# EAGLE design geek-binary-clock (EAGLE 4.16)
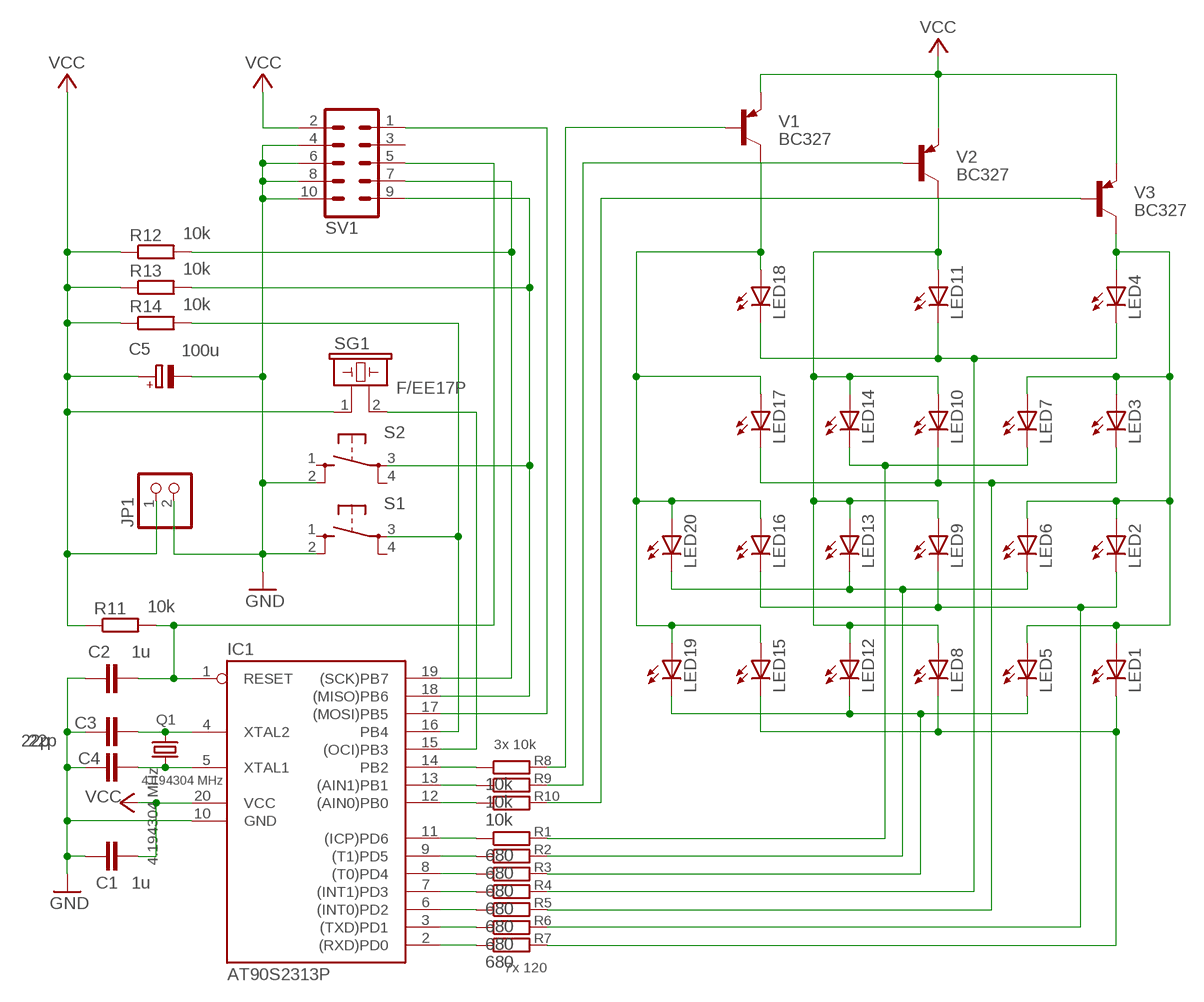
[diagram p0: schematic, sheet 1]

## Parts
C1  1u  C-EU050-025X075  [C050-025X075]
C2  1u  C-EU050-025X075  [C050-025X075]
C3  22p  C-EU025-024X044  [C025-024X044]
C4  22p  C-EU025-024X044  [C025-024X044]
C5  100u  CPOL-EUE15-6AXIAL  [E15-6]
IC1  AT90S2313P  [DIL20]
JP1  PINHD-1X2  [1X02]
LED1  LED5MM  [LED5MM]
LED2  LED5MM  [LED5MM]
LED3  LED5MM  [LED5MM]
LED4  LED5MM  [LED5MM]
LED5  LED5MM  [LED5MM]
LED6  LED5MM  [LED5MM]
LED7  LED5MM  [LED5MM]
LED8  LED5MM  [LED5MM]
LED9  LED5MM  [LED5MM]
LED10  LED5MM  [LED5MM]
LED11  LED5MM  [LED5MM]
LED12  LED5MM  [LED5MM]
LED13  LED5MM  [LED5MM]
LED14  LED5MM  [LED5MM]
LED15  LED5MM  [LED5MM]
LED16  LED5MM  [LED5MM]
LED17  LED5MM  [LED5MM]
LED18  LED5MM  [LED5MM]
LED19  LED5MM  [LED5MM]
LED20  LED5MM  [LED5MM]
Q1  4.194304 MHz  HC49U-V  [HC49U-V]
R1  680  R-EU_0207/10  [0207/10]
R2  680  R-EU_0207/10  [0207/10]
R3  680  R-EU_0207/10  [0207/10]
R4  680  R-EU_0207/10  [0207/10]
R5  680  R-EU_0207/10  [0207/10]
R6  680  R-EU_0207/10  [0207/10]
R7  680  R-EU_0207/10  [0207/10]
R8  10k  R-EU_0207/10  [0207/10]
R9  10k  R-EU_0207/10  [0207/10]
R10  10k  R-EU_0207/10  [0207/10]
R11  10k  R-EU_0207/10  [0207/10]
R12  10k  R-EU_0207/10  [0207/10]
R13  10k  R-EU_0207/10  [0207/10]
R14  10k  R-EU_0207/10  [0207/10]
S1  10-XX  [B3F-10XX]
S2  10-XX  [B3F-10XX]
SG1  F/EE17P  [F/EE17P]
SV1  ML10L  [ML10L]
V1  BC327  [TO92]
V2  BC327  [TO92]
V3  BC327  [TO92]

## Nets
/RESET: C2.2 IC1.1(RESET) R11.2 SV1.5
A0: LED1.A LED2.A LED3.A LED4.A LED5.A LED6.A LED7.A V3.3(C)
A1: LED8.A LED9.A LED10.A LED11.A LED12.A LED13.A LED14.A V2.3(C)
A2: LED15.A LED16.A LED17.A LED18.A LED19.A LED20.A V1.3(C)
D0: LED1.K(C) LED8.K(C) LED15.K(C) R7.2
D1: LED2.K(C) LED9.K(C) LED16.K(C) R6.2
D2: LED3.K(C) LED10.K(C) LED17.K(C) R5.2
D3: LED4.K(C) LED11.K(C) LED18.K(C) R4.2
D4: LED5.K(C) LED12.K(C) LED19.K(C) R3.2
D5: LED6.K(C) LED13.K(C) LED20.K(C) R2.2
D6: LED7.K(C) LED14.K(C) R1.2
GND: C1.1 C2.1 C3.1 C4.1 C5.- IC1.10(GND) JP1.2 S1.2 S2.2 SV1.4 SV1.6 SV1.8 SV1.10
N$1: IC1.11((ICP)PD6) R1.1
N$2: IC1.9((T1)PD5) R2.1
N$3: IC1.8((T0)PD4) R3.1
N$4: IC1.7((INT1)PD3) R4.1
N$5: IC1.6((INT0)PD2) R5.1
N$6: IC1.3((TXD)PD1) R6.1
N$7: IC1.2((RXD)PD0) R7.1
N$8: C3.2 IC1.4(XTAL2) Q1.1
N$9: IC1.16(PB4) R14.2 S1.3
N$10: R9.2 V2.2(B)
N$11: R10.2 V3.2(B)
N$12: R8.2 V1.2(B)
N$13: IC1.12((AIN0)PB0) R10.1
N$14: IC1.13((AIN1)PB1) R9.1
N$15: IC1.14(PB2) R8.1
N$16: C4.2 IC1.5(XTAL1) Q1.2
N$17: IC1.15((OCI)PB3) SG1.2
PB5: IC1.17((MOSI)PB5) SV1.1
PB6: IC1.18((MISO)PB6) R13.2 S2.3 SV1.9
PB7: IC1.19((SCK)PB7) R12.2 SV1.7
VCC: C1.2 C5.+ IC1.20(VCC) JP1.1 R11.1 R12.1 R13.1 R14.1 SG1.1 SV1.2 V1.1(E) V2.1(E) V3.1(E)
Unconnected: S1.1 S1.4 S2.1 S2.4 SV1.3

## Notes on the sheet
- 3x 10k
- 4.194304 MHz
- 7x 120

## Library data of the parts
C1-C4 = rcl:C-EU: CAPACITOR, European symbol
C5 = rcl:CPOL-EU: POLARIZED CAPACITOR, European symbol
IC1 = avr:AT90S2313: MICROCONTROLLER 2 Kbytes FLASH 128 bytes SRAM 128 bytes EEPROM UART
JP1 = pinhead:PINHD-1X2: PIN HEADER
LED1-LED20 = led:LED: LED
Q1 = QUARTZ:HC49U-V
R1-R14 = rcl:R-EU_: RESISTOR, European symbol
S1 S2 = KEYOMRON:10-XX
SG1 = buzzer:F/EE17P: BUZZER
SV1 = con-harting-ml:ML10: HARTING
V1-V3 = transistor-pnp:BC327: PNP Transistor

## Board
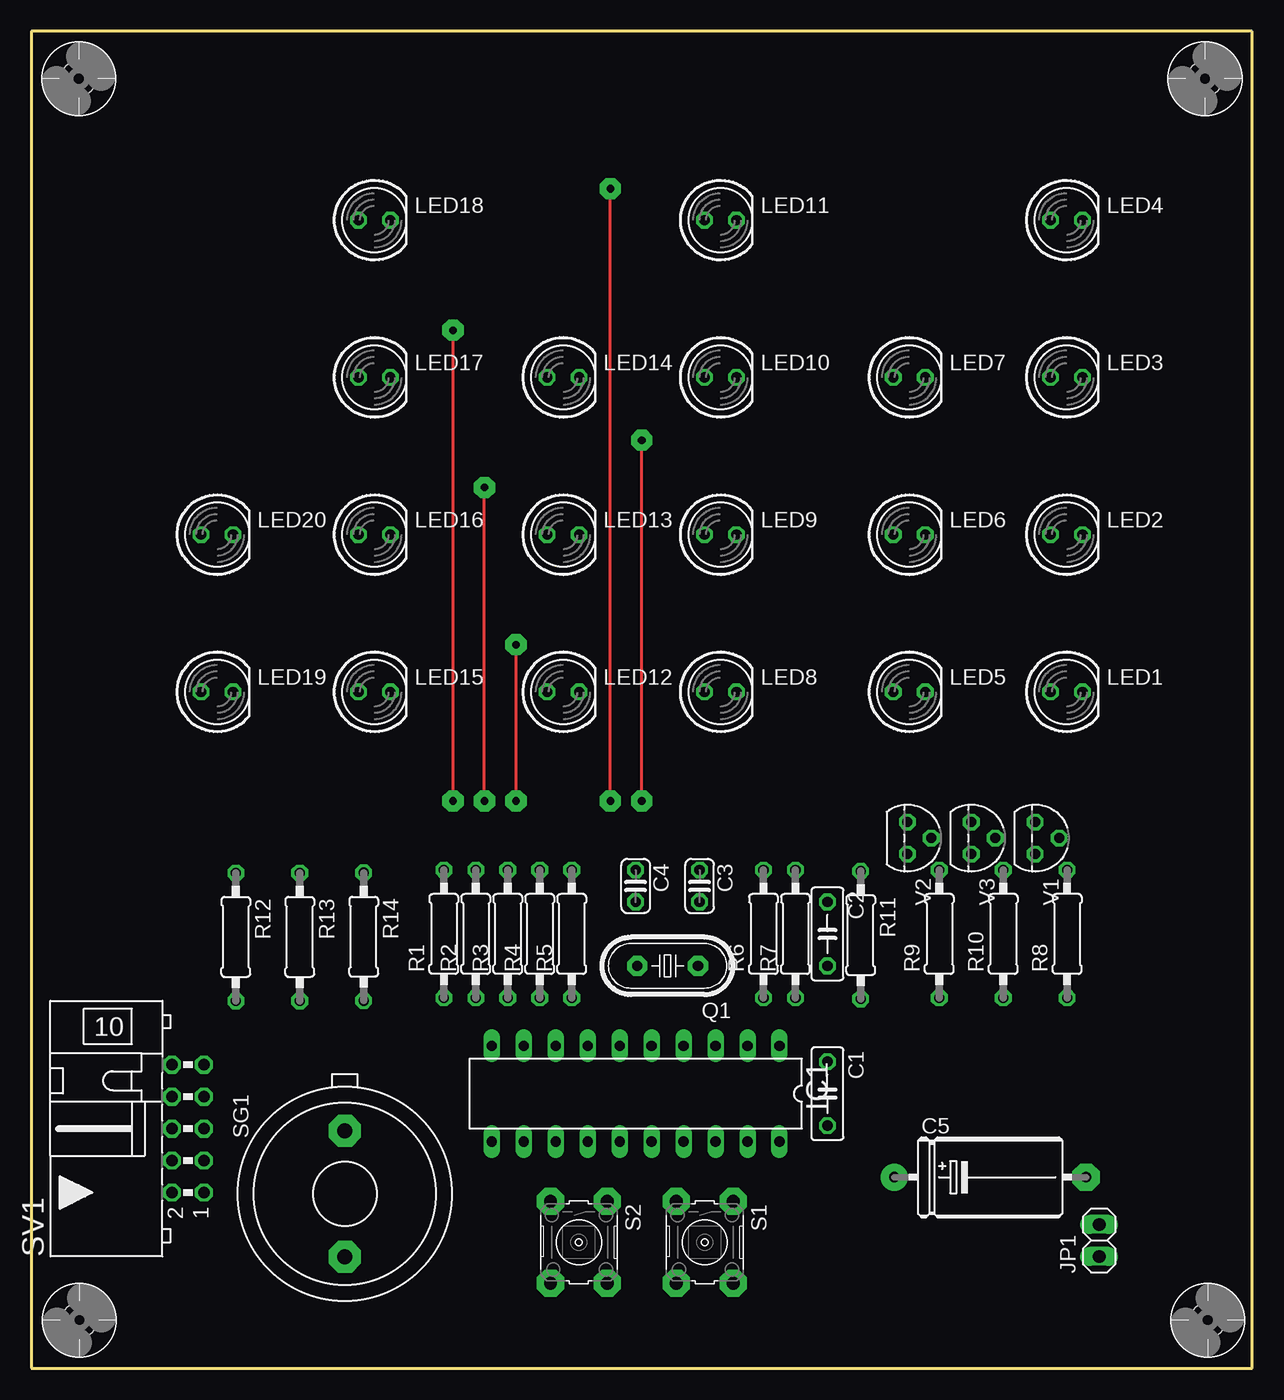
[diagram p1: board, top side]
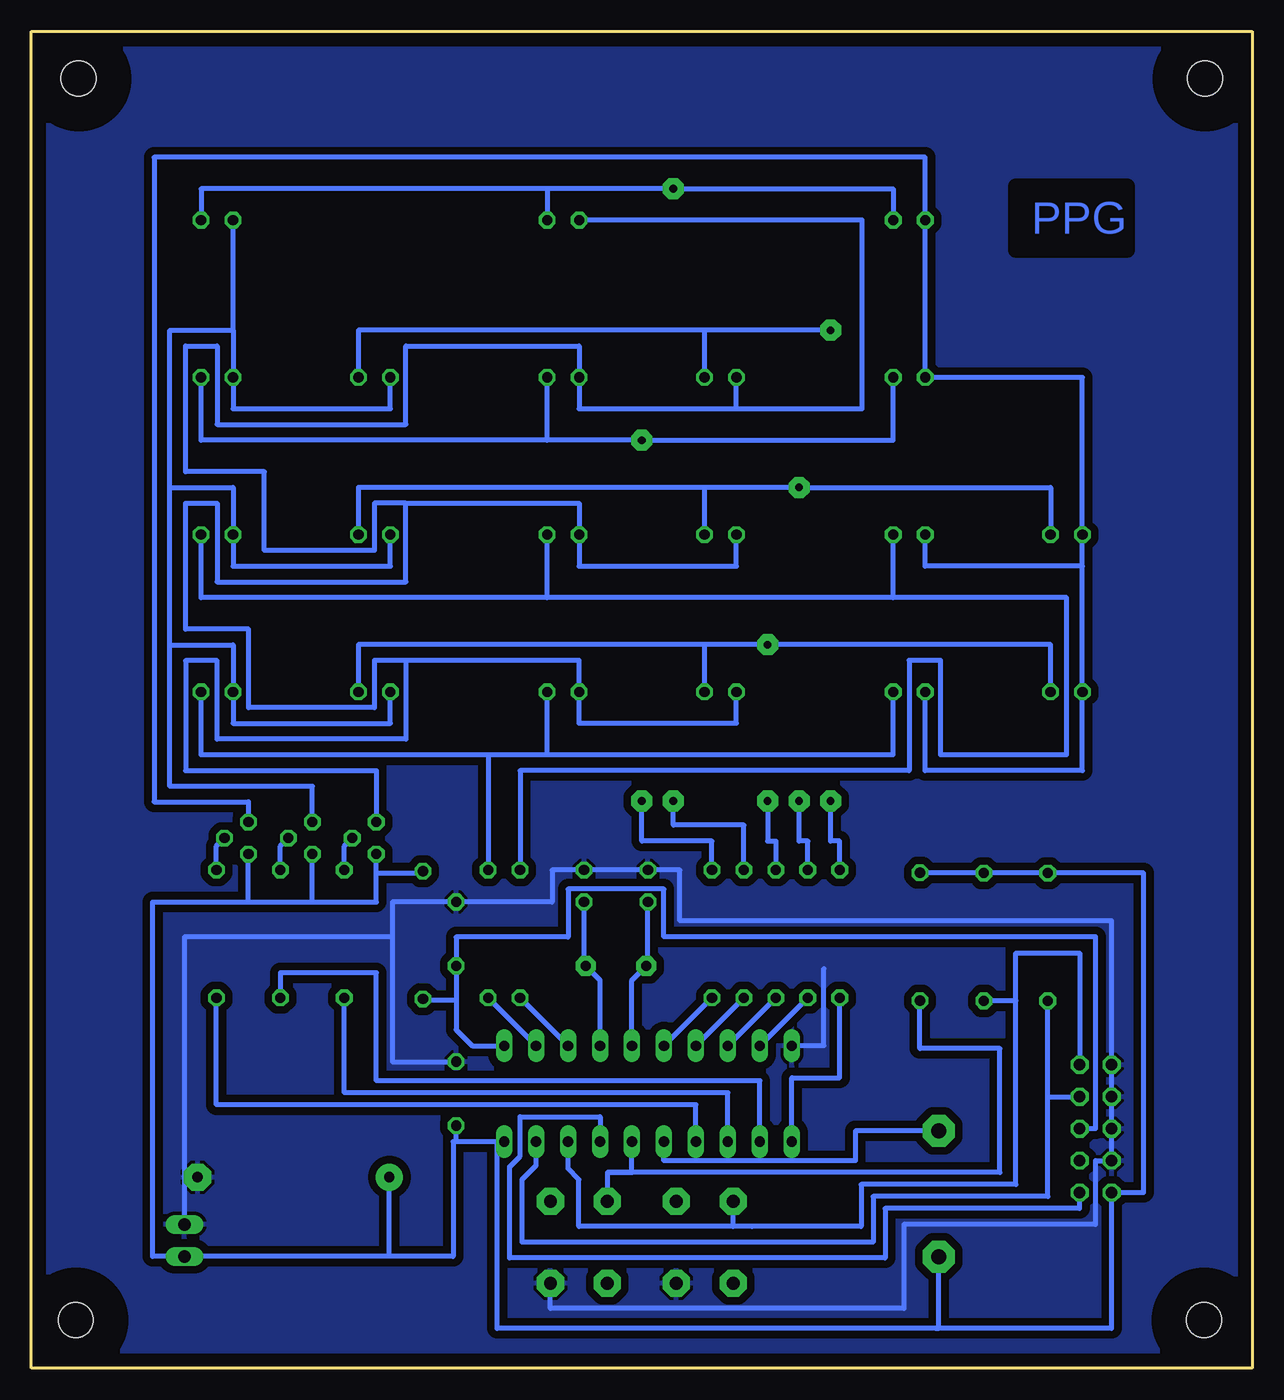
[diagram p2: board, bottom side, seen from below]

Size 97 x 106.25 mm. Coordinates in mm from the lower left corner, seen from the top.
Outline: 0,0 97,0 97,106.25 0,106.25 0,0
Copper layers (1*16): Top 0.035mm / dielectric 1.5mm / Bottom 0.035mm
Design rules "default": minimum track width 10mil, minimum drill 24mil, track to track 8mil, track to pad 8mil, pad to pad 8mil, via to via 8mil, smd to smd 8mil, copper to edge 40mil, drill to drill 8mil, minimum pad ring 10mil, minimum via ring 8mil, stop-mask expansion 4mil, vias tented up to drill 0mil, thermal gap 10mil
bRestrict: area 9.9,88.9 to 18.8,94

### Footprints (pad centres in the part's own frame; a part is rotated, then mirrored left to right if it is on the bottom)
C050-025X075 = drill 0.813 octagon: 1 -2.54,0; 2 2.54,0
C025-024X044 = drill 0.813 octagon: 1 -1.27,0; 2 1.27,0
E15-6 = drill 0.813 pad 2.159 round: + -7.62,0 | drill 0.813 pad 2.159 octagon: - 7.62,0
DIL20 = drill 0.813 long: 1 -11.43,-3.81; 2 -8.89,-3.81; 3 -6.35,-3.81; 4 -3.81,-3.81; 5 -1.27,-3.81; 6 1.27,-3.81; 7 3.81,-3.81; 8 6.35,-3.81; 9 8.89,-3.81; 10 11.43,-3.81; 11 11.43,3.81; 12 8.89,3.81; 13 6.35,3.81; 14 3.81,3.81; 15 1.27,3.81; 16 -1.27,3.81; 17 -3.81,3.81; 18 -6.35,3.81; 19 -8.89,3.81; 20 -11.43,3.81
1X02 = drill 1.016 long: 1 -1.27,0; 2 1.27,0
LED5MM = drill 0.813 octagon: A -1.27,0; K 1.27,0
HC49U-V = drill 0.813 pad 1.6 octagon: 1 -2.413,0; 2 2.413,0
0207/10 = drill 0.813 octagon: 1 -5.08,0; 2 5.08,0
B3F-10XX = drill 1.016 pad 2.159 octagon: 1 -3.251,2.261; 2 3.251,2.261; 3 -3.251,-2.261; 4 3.251,-2.261
F/EE17P = drill 1.194 pad 2.54 octagon: 1 -5.004,0; 2 5.004,0
ML10L = drill 0.914 octagon: 1 -5.08,-1.27; 2 -5.08,1.27; 3 -2.54,-1.27; 4 -2.54,1.27; 5 0,-1.27; 6 0,1.27; 7 2.54,-1.27; 8 2.54,1.27; 9 5.08,-1.27; 10 5.08,1.27
BO2,8 = hole 2.794: 0,0
TO92 = drill 0.813 octagon: 1 1.27,0; 2 0,1.905; 3 -1.27,0

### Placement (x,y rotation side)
C1  63.25,21.81 270 top
C2  63.25,34.51 270 top
C3  53.09,38.32 270 top
C4  48.01,38.32 270 top
C5  76.18,15.17 0 top
IC1  48.01,21.81 180 top
JP1  84.84,10.14 90 top
LED1  82.25,53.75 0 top
LED2  82.25,66.25 0 top
LED3  82.25,78.75 0 top
LED4  82.25,91.25 0 top
LED5  69.75,53.75 0 top
LED6  69.75,66.25 0 top
LED7  69.75,78.75 0 top
LED8  54.75,53.75 0 top
LED9  54.75,66.25 0 top
LED10  54.75,78.75 0 top
LED11  54.75,91.25 0 top
LED12  42.25,53.75 0 top
LED13  42.25,66.25 0 top
LED14  42.25,78.75 0 top
LED15  27.25,53.75 0 top
LED16  27.25,66.25 0 top
LED17  27.25,78.75 0 top
LED18  27.25,91.25 0 top
LED19  14.75,53.75 0 top
LED20  14.75,66.25 0 top
Q1  50.55,31.97 180 top
R1  32.77,34.51 90 top
R2  35.31,34.51 90 top
R3  37.85,34.51 90 top
R4  40.39,34.51 90 top
R5  42.93,34.51 90 top
R6  58.17,34.51 90 top
R7  60.71,34.51 90 top
R8  82.3,34.51 90 top
R9  72.14,34.51 90 top
R10  77.22,34.51 90 top
R11  65.89,34.42 270 top
R12  16.24,34.27 270 top
R13  21.32,34.27 270 top
R14  26.4,34.29 270 top
S1  53.5,10 270 top
S2  43.5,10 270 top
SG1  24.91,13.85 90 top
SV1  12.43,19.03 90 top
U$1  [BO2,8]  93.25,102.5 0 top
U$2  [BO2,8]  3.81,3.81 0 top
U$3  [BO2,8]  93.48,3.81 0 top
U$15  [BO2,8]  3.75,102.5 0 top
V1  79.76,42.13 270 top
V2  69.6,42.13 270 top
V3  74.68,42.13 270 top

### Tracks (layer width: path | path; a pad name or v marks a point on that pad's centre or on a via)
/RESET
  Bottom 0.406: IC1.1 61.98,25.62 63.25,26.89 63.25,29.21 | 63.25,31.73 63.25,29.21 | 63.25,31.73 C2.2 | SV1.5 12.43,19.03 12.43,34.29 46.74,34.29 46.74,38.08 54.36,38.08 54.36,34.27 63.25,34.27 63.25,31.73 | R11.2 65.89,29.21 63.25,29.21
A0
  Bottom 0.406: LED7.A 68.48,76.25 80.98,76.25 LED3.A 80.98,82.5 | 80.98,82.5 LED4.A | 86,70 80.98,70 LED2.A 80.98,63.75 68.48,63.75 LED6.A | 86,70 86,82.5 80.98,82.5 | 86,57.48 80.98,57.48 LED1.A 80.98,51.25 68.48,51.25 LED5.A | 86,57.48 86,70 | 86,57.48 86,46.25 74.68,46.25 V3.3
A1
  Bottom 0.406: 41,76.25 53.48,76.25 LED10.A 53.48,81.25 67.25,81.25 67.25,75 82.25,75 82.25,81.25 84.75,81.25 84.75,71.25 78.5,71.25 78.5,65 69.75,65 69.75,68.75 67.25,68.75 | 41,76.25 40.98,76.25 | LED13.A 40.98,63.75 53.48,63.75 LED9.A 53.48,68.75 67.25,68.75 | LED12.A 40.98,51.25 53.48,51.25 LED8.A 53.48,56.25 67.25,56.25 | 67.25,56.25 69.75,56.25 69.75,52.5 79.75,52.5 79.75,58.73 84.75,58.73 84.75,68.75 82.25,68.75 82.25,62.5 67.25,62.5 67.25,68.75 | 67.25,56.25 67.25,50 82.25,50 82.25,56.23 84.75,56.23 84.75,47.5 69.6,47.5 V2.3 | LED11.A 31,91.25 31,76.25 41,76.25 | LED14.A 41,78.75 41,76.25
A2
  Bottom 0.406: LED16.A 25.98,63.75 13.48,63.75 | 13.48,63.75 LED20.A 13.48,78.75 LED17.A LED18.A 25.98,96.25 87.25,96.25 87.25,45 79.76,45 V1.3 | 13.48,63.75 LED19.A 13.48,47.5 25.98,47.5 LED15.A
D0
  Bottom 0.406: LED1.K 83.52,48.75 60.71,48.75 | 56.02,48.75 LED8.K | 56.02,48.75 60.71,48.75 | LED15.K 28.52,48.75 56,48.75 | 56,48.75 56.02,48.75 | 60.71,48.75 R7.2 | 56,48.75 60.71,48.75
D1
  Bottom 0.406: 28.52,61.25 LED16.K | 28.52,61.25 56.02,61.25 | 56.02,61.25 LED9.K | LED2.K 83.52,61.25 56.02,61.25 | 28.52,61.25 14.75,61.25 14.75,48.75 24.75,48.75 24.75,56.25 27.25,56.25 27.25,47.5 58.17,47.5 R6.2
D2  (via drill 0.61 pad 1.68)
  Top 0.254: v48.5,45.08 v48.5,73.75
  Bottom 0.406: LED17.K 28.52,73.75 v48.5,73.75 56.02,73.75 | 56.02,73.75 LED10.K | LED3.K 83.52,73.75 56.02,73.75 | v48.5,45.08 48.5,41.89 42.93,41.89 R5.2
D3  (via drill 0.61 pad 1.68)
  Top 0.254: v46,45.08 v46,93.75
  Bottom 0.406: LED18.K 28.52,93.75 v46,93.75 56.02,93.75 | 56.02,93.75 LED11.K | LED4.K 83.52,93.75 56.02,93.75 | v46,45.08 46,43.16 40.39,43.16 R4.2
D4  (via drill 0.61 pad 1.68)
  Top 0.254: v38.5,57.5 v38.5,45.08
  Bottom 0.406: LED5.K 71.02,57.5 43.52,57.5 | 43.52,57.5 LED12.K | LED19.K 16.02,57.5 v38.5,57.5 43.52,57.5 | v38.5,45.08 38.5,41.89 37.85,41.89 R3.2
D5  (via drill 0.61 pad 1.68)
  Top 0.254: v36,45.08 v36,70
  Bottom 0.406: 43.52,70 LED13.K | LED6.K 71.02,70 43.52,70 | LED20.K 16.02,70 v36,70 43.52,70 | v36,45.08 36,41.89 35.31,41.89 R2.2
D6  (via drill 0.61 pad 1.68)
  Top 0.254: v33.5,45.08 v33.5,82.5
  Bottom 0.406: LED7.K 71.02,82.5 43.52,82.5 | 43.52,82.5 LED14.K | v33.5,82.5 43.52,82.5 | v33.5,45.08 33.5,41.89 32.77,41.89 R1.2
GND
  Bottom 0.406: C1.1 68.33,24.35 68.33,34.27 | 68.33,34.27 68.33,37.05 C2.1 55.63,37.05 55.63,39.59 C3.1 C4.1 45.47,39.59 45.47,35.56 11.16,35.56 SV1.10 SV1.8 SV1.6 SV1.4 12.43,16.49 12.43,11.41 27.67,11.41 27.67,4.74 55.76,4.74 S1.2 | 84.84,15.22 84.84,34.27 68.33,34.27 | 84.84,15.22 JP1.2 | IC1.10 34.04,25.62 34.04,31.75 | C5.- 83.8,15.24 84.84,15.24 84.84,15.22
  pour Bottom (isolate 0.61): 1.25,105 95.75,105 95.75,1.25 1.25,1.25
N$1
  Bottom 0.406: R1.1 32.77,23.08 36.58,23.08 IC1.11
N$2
  Bottom 0.406: R2.1 IC1.9
N$3
  Bottom 0.406: R3.1 IC1.8
N$4
  Bottom 0.406: R4.1 IC1.7
N$5
  Bottom 0.406: R5.1 IC1.6
N$6
  Bottom 0.406: IC1.3 R6.1
N$7
  Bottom 0.406: IC1.2 R7.1
N$8
  Bottom 0.406: IC1.4 51.82,30.83 Q1.1 53.09,32.1 C3.2
N$9
  Bottom 0.406: 51.24,15.56 S1.3 | IC1.16 49.28,15.56 51.24,15.56 | R14.2 26.4,25.4 20.05,25.4 20.05,15.56 51.24,15.56
N$10
  Bottom 0.406: V2.2 72.14,41.49 R9.2
N$11
  Bottom 0.406: V3.2 77.22,41.49 R10.2
N$12
  Bottom 0.406: V1.2 82.3,41.49 R8.2
N$13
  Bottom 0.406: R10.1 77.22,31.41 69.6,31.41 69.6,22.84 39.12,22.84 IC1.12
N$14
  Bottom 0.406: R9.1 72.14,21.89 41.66,21.89 IC1.13
N$15
  Bottom 0.406: R8.1 82.3,20.93 44.2,20.93 IC1.14
N$16
  Bottom 0.406: IC1.5 49.28,30.83 Q1.2 48.01,32.1 C4.2
N$17
  Bottom 0.406: IC1.15 46.74,16.49 31.52,16.49 31.52,18.85 SG1.2
PB5
  Bottom 0.406: IC1.17 51.82,19.98 58.17,19.98 58.17,16.83 59,16 59,8.75 29.16,8.75 29.16,12.68 13.7,12.68 SV1.1
PB6
  Bottom 0.406: 39.75,11.25 31.07,11.25 31.07,14.59 18.78,14.59 18.78,29.21 | SV1.9 13.7,33 18.78,33 18.78,29.21 | R13.2 18.78,29.19 18.78,29.21 | S2.3 41.24,11.25 39.75,11.25 | IC1.18 54.36,15.86 53.5,15 53.5,11.25 39.75,11.25
PB7
  Bottom 0.406: 16.24,21.57 SV1.7 | 16.24,21.57 16.24,13.63 30.11,13.63 30.11,10 58,10 58,15 56.9,16.1 IC1.19 | 16.24,21.57 R12.2
VCC
  Bottom 0.406: 69.6,39.37 69.6,37.05 74.68,37.05 | 69.6,39.37 V2.1 | 74.68,37.05 V3.1 | 79.76,37.05 V1.1 | 79.76,37.05 74.68,37.05 | 79.76,37.05 87.38,37.05 87.38,8.87 JP1.1 84.84,8.89 68.56,8.89 | 63.25,18 IC1.20 60,18 60,3.15 25.13,3.15 | 63.25,18 C1.2 | 25.13,3.15 11.16,3.15 SV1.2 8.62,13.95 8.62,39.35 R12.1 R13.1 26.4,39.35 R14.1 | SG1.1 24.91,3.15 25.13,3.15 | 63.5,8.89 63.5,8.87 | 63.5,8.89 68.56,8.89 | 63.25,18 63.5,18 63.5,8.89 | R11.1 65.89,39.37 69.6,39.37 | 68.56,8.89 C5.+ | 68.56,8.89 68.58,8.89

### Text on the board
Bottom: PPG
